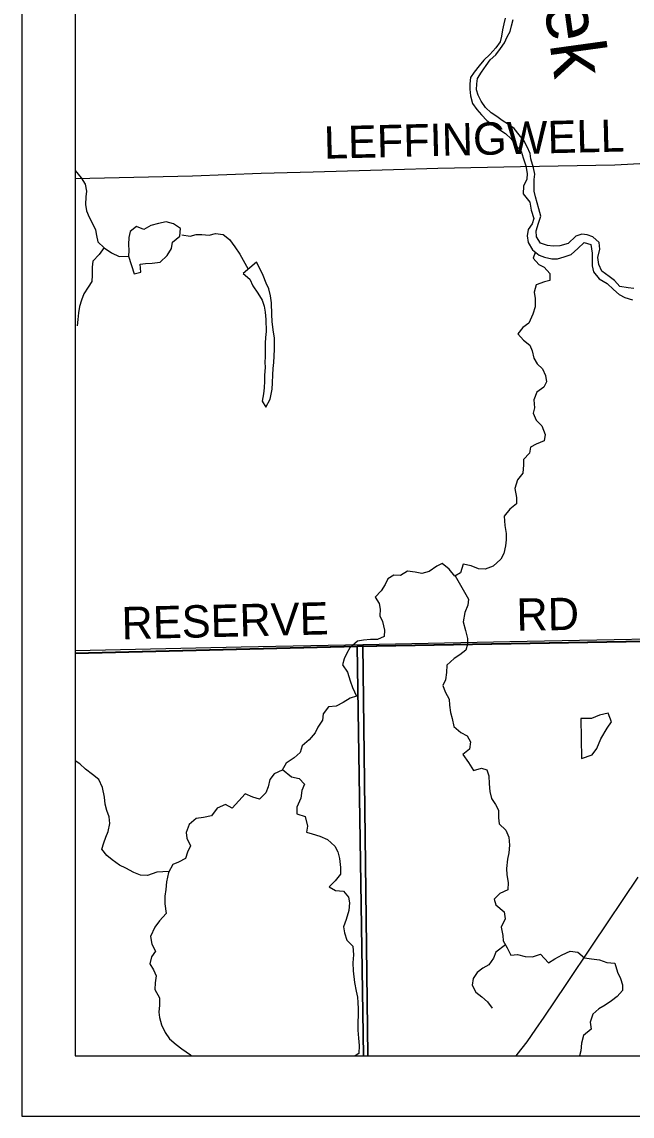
# Model space of a CAD drawing. Extents: x 0 to 34, y 0 to 22.
# Drawn here: x 2.63 to 3.7, y 9.902 to 11.824 of the extents above; entities that cross this region are included whole.
import ezdxf

# ---------------------------------------------------------------- set-up
doc = ezdxf.new("R2010")
doc.units = 0
for name, color, linetype in [('GM_X_Corporation', 7, 'Continuous'), ('GM_X_County_Road', 7, 'Continuous'), ('GM_X_County_Road_Text', 7, 'Continuous'), ('GM_X_Minor_Lake', 7, 'Continuous'), ('GM_X_Minor_River', 7, 'Continuous'), ('GM_X_Minor_River_Text', 7, 'Continuous'), ('GM_X_Rail_Line', 7, 'Continuous'), ('GM_X_Township_Road', 7, 'Continuous'), ('SH_Data', 7, 'Continuous')]:
    doc.layers.add(name, color=color, linetype=linetype)

msp = doc.modelspace()

# ---------------------------------------------------------------- linework, layer by layer
at = {"layer": 'GM_X_Corporation'}
msp.add_lwpolyline([(6.7217, 15.9197), (5.5749, 15.8972), (5.1967, 15.8898), (4.4889, 15.8766), (2.7231, 15.8419), (2.7231, 10.7149), (3.2181, 10.7269), (4.6326, 10.7519), (5.2789, 10.7635), (5.571, 10.7686), (6.8097, 10.7901)], dxfattribs=at)
for points in [[(3.2288, 10.0075), (9.4322, 10.0075), (9.4266, 10.7304), (9.4256, 10.8527), (9.3392, 10.8506), (8.3328, 10.8251), (7.8767, 10.8135), (6.8339, 10.7907), (6.8097, 10.7901), (5.571, 10.7686), (5.2789, 10.7635), (4.6326, 10.7519), (3.2181, 10.7269)], [(3.2368, 10.0075), (4.267, 10.0075), (4.2548, 10.7474), (3.913, 10.7427), (3.486, 10.7347), (3.228, 10.7293)], [(2.7231, 10.7186), (2.7231, 10.0075), (3.2368, 10.0075), (3.228, 10.7293), (3.0146, 10.725)], [(2.7231, 10.7149), (2.7231, 10.0075), (3.2288, 10.0075), (3.2181, 10.7269)]]:
    msp.add_lwpolyline(points, close=True, dxfattribs=at)
at = {"layer": 'GM_X_County_Road'}
msp.add_line((2.7231, 10.7143), (3.2183, 10.7263), dxfattribs=at)
for points in [[(4.6159, 11.5926), (4.1469, 11.5863), (3.7686, 11.5769), (3.6702, 11.5721), (3.5046, 11.5687), (3.3595, 11.566), (3.2817, 11.5638), (3.1404, 11.5595), (3.0493, 11.5571), (2.9289, 11.5524), (2.7231, 11.5477)], [(3.2183, 10.7263), (4.6328, 10.7513), (5.2791, 10.763), (5.5712, 10.7681), (6.8099, 10.7896)]]:
    msp.add_lwpolyline(points, dxfattribs=at)
at = {"layer": 'GM_X_Minor_Lake'}
for points in [[(2.8266, 11.3808), (2.8386, 11.3841), (2.8369, 11.3977), (2.8467, 11.3994), (2.8584, 11.3997), (2.872, 11.4014), (2.8843, 11.4131), (2.8921, 11.4257), (2.8941, 11.4368), (2.9068, 11.4473), (2.9077, 11.4606), (2.8958, 11.4687), (2.8829, 11.4723), (2.8696, 11.4694), (2.8557, 11.4657), (2.8437, 11.459), (2.8307, 11.4641), (2.8195, 11.4555), (2.8171, 11.4448), (2.8169, 11.4327), (2.8171, 11.4217), (2.8169, 11.4122)], [(2.8169, 11.4122), (2.8266, 11.3808)], [(3.0179, 11.3814), (3.0298, 11.3717), (3.035, 11.3597), (3.0436, 11.3469), (3.051, 11.3345), (3.0546, 11.3243), (3.0567, 11.3134), (3.0577, 11.3009), (3.0581, 11.2796), (3.0571, 11.2693), (3.0565, 11.259), (3.0563, 11.2495), (3.0562, 11.2355), (3.056, 11.226), (3.0562, 11.2165), (3.0553, 11.2028), (3.0551, 11.1925), (3.0546, 11.1808), (3.0533, 11.1705), (3.0512, 11.1575), (3.0579, 11.147), (3.0652, 11.1608), (3.069, 11.1784), (3.0696, 11.1894), (3.0701, 11.2035), (3.0706, 11.2149), (3.0716, 11.2255), (3.0725, 11.2366), (3.0726, 11.2487), (3.0729, 11.2582), (3.0727, 11.2681), (3.0705, 11.2825), (3.0687, 11.2973), (3.0681, 11.3098), (3.0677, 11.3299), (3.066, 11.3424), (3.0627, 11.3545), (3.0584, 11.3647), (3.0532, 11.3783), (3.0481, 11.388), (3.041, 11.4012)], [(3.041, 11.4012), (3.0179, 11.3814)], [(3.6115, 10.5296), (3.6303, 10.5364), (3.6384, 10.5472), (3.6453, 10.5644), (3.6563, 10.5832), (3.6641, 10.594), (3.6585, 10.6091), (3.643, 10.6058), (3.6291, 10.5998), (3.6102, 10.6002)], [(3.6102, 10.6002), (3.6115, 10.5296)]]:
    msp.add_lwpolyline(points, dxfattribs=at)
at = {"layer": 'GM_X_Minor_River'}
msp.add_line((2.7231, 11.5631), (2.7232, 11.5623), dxfattribs=at)
for points in [[(3.4777, 11.8299), (3.4751, 11.82), (3.4729, 11.8093), (3.4711, 11.7983), (3.4686, 11.7884), (3.4614, 11.7777), (3.4509, 11.7662), (3.4403, 11.7562), (3.432, 11.7466), (3.4234, 11.7352), (3.417, 11.7256), (3.4156, 11.7146), (3.4157, 11.7051), (3.4165, 11.6937), (3.4201, 11.6804), (3.4278, 11.6698), (3.4358, 11.66), (3.4454, 11.6502), (3.4562, 11.6419), (3.4665, 11.6348), (3.478, 11.6273), (3.4883, 11.6179), (3.4956, 11.6077), (3.5056, 11.5963), (3.5092, 11.5846), (3.5138, 11.5708)], [(3.5275, 11.5673), (3.5225, 11.5828), (3.5213, 11.5923), (3.5162, 11.604), (3.51, 11.6154), (3.502, 11.6252), (3.4931, 11.6361), (3.4835, 11.6433), (3.4724, 11.6504), (3.4629, 11.6576), (3.4529, 11.664), (3.4433, 11.673), (3.4353, 11.6843), (3.4302, 11.6946), (3.4275, 11.7044), (3.4278, 11.7147), (3.4292, 11.7242), (3.4363, 11.7349), (3.4442, 11.7471), (3.451, 11.7567), (3.4612, 11.7659), (3.4694, 11.7766), (3.4766, 11.7869), (3.481, 11.7972), (3.4863, 11.8068), (3.4889, 11.8163), (3.4914, 11.8277)], [(3.5138, 11.5708), (3.5163, 11.5575), (3.5157, 11.5473), (3.5095, 11.535), (3.5094, 11.5213), (3.5206, 11.5067), (3.5232, 11.4931), (3.5276, 11.4784), (3.5247, 11.4688), (3.5181, 11.4588), (3.516, 11.4478), (3.5178, 11.436), (3.5252, 11.4232), (3.5371, 11.4136), (3.5467, 11.4104), (3.5592, 11.4076), (3.5695, 11.4074), (3.5811, 11.4106), (3.5932, 11.415), (3.6051, 11.4255), (3.6163, 11.436), (3.6281, 11.4328), (3.6303, 11.4173), (3.6301, 11.4066), (3.6299, 11.3948), (3.6324, 11.3846), (3.6425, 11.3723), (3.6567, 11.3638), (3.6675, 11.3534), (3.6778, 11.3448), (3.6874, 11.3393), (3.7007, 11.3354)], [(2.7232, 11.5623), (2.7337, 11.5496), (2.7407, 11.5387), (2.7432, 11.5262), (2.7419, 11.516), (2.7413, 11.5027), (2.7431, 11.4917), (2.7478, 11.4808), (2.7529, 11.4706), (2.7585, 11.4585), (2.7605, 11.4483), (2.763, 11.437), (2.7742, 11.4269), (2.7869, 11.4181), (2.8002, 11.4115), (2.8169, 11.4122)], [(3.7034, 11.3552), (3.6935, 11.3562), (3.6787, 11.3585), (3.6694, 11.3694), (3.6598, 11.3764), (3.6472, 11.3857), (3.6416, 11.3973), (3.6399, 11.4098), (3.6434, 11.4243), (3.6424, 11.4361), (3.6313, 11.4461), (3.6213, 11.4494), (3.6118, 11.4507), (3.6013, 11.4471), (3.5879, 11.4343), (3.5736, 11.4299), (3.5618, 11.4296), (3.552, 11.431), (3.5398, 11.4349), (3.5328, 11.4458), (3.5322, 11.4564), (3.5361, 11.4698), (3.54, 11.4824), (3.5368, 11.4953), (3.5339, 11.5055), (3.5307, 11.516), (3.5286, 11.5259), (3.5284, 11.5373), (3.5286, 11.5468), (3.5296, 11.5563), (3.5275, 11.5673)], [(2.9102, 11.4492), (2.9246, 11.4469), (2.9356, 11.4501), (2.9454, 11.4503), (2.9583, 11.449), (2.9692, 11.4519), (2.9825, 11.4502), (2.9937, 11.4413), (3.0034, 11.4286), (3.0123, 11.4155), (3.0268, 11.389)], [(2.7737, 11.4274), (2.7653, 11.415), (2.7542, 11.4034), (2.7529, 11.3927), (2.7531, 11.3787), (2.7526, 11.3673), (2.7459, 11.3576), (2.7382, 11.3461), (2.7342, 11.335), (2.731, 11.3236), (2.729, 11.3125), (2.728, 11.3007), (2.7267, 11.2897)], [(3.5306, 11.4189), (3.5302, 11.4184), (3.5266, 11.4085), (3.5367, 11.3973), (3.5462, 11.3925), (3.5559, 11.3813), (3.5561, 11.3695), (3.5463, 11.3667), (3.532, 11.3615), (3.5285, 11.3489), (3.5302, 11.3375), (3.5301, 11.3231), (3.5262, 11.3104), (3.5193, 11.2944), (3.5084, 11.2866), (3.4999, 11.2758), (3.5096, 11.2642), (3.5207, 11.2556), (3.5251, 11.2459), (3.5276, 11.233), (3.5335, 11.2232), (3.5431, 11.2139), (3.5483, 11.2022), (3.55, 11.1912), (3.5456, 11.1817), (3.5329, 11.1731), (3.5278, 11.1597), (3.5292, 11.1457), (3.5267, 11.1361), (3.5319, 11.1237), (3.5419, 11.114), (3.5475, 11.0989), (3.5462, 11.0875), (3.5319, 11.0819), (3.5222, 11.0768), (3.5201, 11.0661), (3.5097, 11.0549), (3.5099, 11.0454), (3.5086, 11.0309), (3.4994, 11.0194), (3.4947, 11.0041), (3.4977, 10.9882), (3.4975, 10.9768), (3.4855, 10.9678), (3.4755, 10.9551), (3.477, 10.9388), (3.4791, 10.9252), (3.479, 10.9138), (3.478, 10.9035), (3.4752, 10.8898), (3.4701, 10.8798), (3.4567, 10.8674), (3.4424, 10.8622), (3.4306, 10.8627), (3.4177, 10.8682), (3.404, 10.8709), (3.3993, 10.856), (3.3892, 10.8498), (3.3795, 10.8625), (3.3672, 10.8725), (3.3574, 10.8678), (3.3443, 10.8584), (3.3315, 10.8544), (3.3194, 10.8572), (3.3061, 10.8588), (3.2937, 10.8514), (3.2823, 10.8515), (3.2715, 10.8456), (3.2671, 10.8353), (3.2601, 10.8245), (3.2493, 10.8133), (3.2563, 10.8021), (3.2584, 10.7922), (3.2579, 10.7801), (3.2622, 10.7703), (3.2656, 10.7551), (3.265, 10.7441), (3.2534, 10.7386), (3.2412, 10.7387), (3.2287, 10.7377), (3.2185, 10.736), (3.2051, 10.7244), (3.2, 10.7148), (3.1953, 10.7048), (3.192, 10.6941), (3.201, 10.6814), (3.2058, 10.6663), (3.2098, 10.6546), (3.2169, 10.6395), (3.2053, 10.6355), (3.1933, 10.628), (3.1809, 10.6217), (3.1676, 10.6203), (3.1584, 10.6084), (3.1571, 10.5973), (3.1486, 10.5846), (3.1442, 10.5747), (3.1339, 10.5623), (3.1216, 10.5519), (3.1176, 10.54), (3.1075, 10.5307)], [(3.3901, 10.8503), (3.4131, 10.8096), (3.4121, 10.7993), (3.4067, 10.7859), (3.4039, 10.7699), (3.408, 10.7548), (3.4113, 10.7408), (3.4115, 10.7305), (3.4083, 10.7202), (3.3978, 10.7117), (3.3881, 10.7054), (3.3751, 10.6934), (3.3745, 10.6808), (3.3729, 10.6679), (3.3681, 10.6579), (3.3721, 10.647), (3.3792, 10.6342), (3.3801, 10.6232), (3.3815, 10.6103), (3.3847, 10.6001), (3.3877, 10.5857), (3.4, 10.5753), (3.4107, 10.5698), (3.4169, 10.5593), (3.4149, 10.5464), (3.4033, 10.537), (3.4131, 10.5228), (3.422, 10.5089), (3.436, 10.5126), (3.4455, 10.5101), (3.4487, 10.4992), (3.4494, 10.4851), (3.4504, 10.4718), (3.4533, 10.4594), (3.4607, 10.4492), (3.4658, 10.4391), (3.4656, 10.4254), (3.467, 10.4148), (3.4785, 10.404), (3.4841, 10.3916), (3.4851, 10.3775), (3.4842, 10.3638), (3.4818, 10.3532), (3.4798, 10.3364), (3.4804, 10.3254), (3.4829, 10.3122), (3.4824, 10.2988), (3.4681, 10.2925), (3.4584, 10.2828), (3.4613, 10.2726), (3.4759, 10.2604), (3.4773, 10.2479), (3.4707, 10.2333), (3.4736, 10.2189), (3.4742, 10.2094), (3.4809, 10.197), (3.4872, 10.1846), (3.4989, 10.1856), (3.5126, 10.182), (3.5255, 10.1815), (3.5394, 10.186), (3.5533, 10.171), (3.5649, 10.1781), (3.5773, 10.1848), (3.5916, 10.1915), (3.6049, 10.1895), (3.6165, 10.1795), (3.629, 10.1778), (3.643, 10.1762), (3.656, 10.1715), (3.6697, 10.1702), (3.6745, 10.1547), (3.6796, 10.1434), (3.6836, 10.1321), (3.6834, 10.1222), (3.6742, 10.1118), (3.6641, 10.104), (3.6532, 10.0966), (3.6416, 10.0899), (3.6315, 10.0806), (3.6265, 10.0668), (3.6282, 10.0543), (3.6152, 10.0434), (3.6113, 10.0297), (3.6104, 10.0164), (3.608, 10.0075)], [(2.8875, 10.331), (2.8661, 10.3301), (2.8503, 10.3245), (2.8378, 10.325), (2.826, 10.3294), (2.8118, 10.3371), (2.8011, 10.3422), (2.7881, 10.3518), (2.7784, 10.3596), (2.7699, 10.3705), (2.7735, 10.3816), (2.7771, 10.3915), (2.7811, 10.4015), (2.7838, 10.4156), (2.7829, 10.4273), (2.7785, 10.4383), (2.776, 10.4496), (2.7743, 10.4617), (2.7713, 10.4788), (2.7646, 10.4931), (2.7538, 10.5016), (2.7415, 10.5113), (2.7311, 10.5202), (2.7231, 10.5255)], [(3.1075, 10.5307), (3.0933, 10.5213), (3.086, 10.509), (3.0724, 10.5031), (3.0647, 10.493), (3.0619, 10.4797), (3.0579, 10.4694), (3.0468, 10.4581), (3.0346, 10.4621), (3.0212, 10.4675), (3.0104, 10.4552), (2.9985, 10.4428), (2.9871, 10.4487), (2.972, 10.4423), (2.9621, 10.4288), (2.9481, 10.4259), (2.9356, 10.4245), (2.9229, 10.4136), (2.9179, 10.3995), (2.9188, 10.39), (2.9255, 10.3765), (2.9204, 10.365), (2.9168, 10.3539), (2.9044, 10.3476), (2.8947, 10.3436), (2.8866, 10.3294), (2.8835, 10.3134), (2.8822, 10.2997), (2.8802, 10.2879), (2.8804, 10.2746), (2.883, 10.2575), (2.8711, 10.2444), (2.8626, 10.2336), (2.855, 10.2171), (2.8579, 10.2039), (2.8642, 10.1911), (2.8568, 10.1814), (2.854, 10.1689), (2.8606, 10.1583), (2.865, 10.1482), (2.8633, 10.136), (2.8628, 10.1238), (2.871, 10.1092), (2.8712, 10.0963), (2.8699, 10.0845), (2.8712, 10.0746), (2.8745, 10.0621), (2.8808, 10.0486), (2.8886, 10.0373), (2.9005, 10.0277), (2.9101, 10.0199), (2.9255, 10.0092), (2.9274, 10.0075)], [(3.0867, 10.5102), (3.1029, 10.4976), (3.1162, 10.4948), (3.1254, 10.4847), (3.1207, 10.4736), (3.1191, 10.4603), (3.1122, 10.4442), (3.112, 10.4328), (3.1265, 10.4277), (3.131, 10.4111), (3.1289, 10.4004), (3.1392, 10.3972), (3.1521, 10.3933), (3.1659, 10.3875), (3.1786, 10.3759), (3.1841, 10.3658), (3.1866, 10.3544), (3.1888, 10.3381), (3.1886, 10.3267), (3.1794, 10.3148), (3.169, 10.3043), (3.1801, 10.2981), (3.1941, 10.2968), (3.2026, 10.286), (3.2047, 10.2761), (3.2034, 10.2628), (3.1988, 10.2472), (3.1941, 10.2342), (3.1955, 10.2235), (3.1995, 10.2107), (3.2103, 10.2003), (3.2117, 10.1847), (3.2101, 10.171), (3.2107, 10.1566), (3.2134, 10.1361), (3.2163, 10.121), (3.2184, 10.1108), (3.2189, 10.1013), (3.2199, 10.0903), (3.2197, 10.08), (3.2188, 10.0652), (3.2191, 10.0527), (3.2205, 10.0386), (3.2215, 10.0254), (3.2206, 10.0117), (3.2142, 10.0075)], [(3.4781, 10.2023), (3.4613, 10.1894), (3.4573, 10.1791), (3.4488, 10.1675), (3.4383, 10.1617), (3.4286, 10.1539), (3.4212, 10.1435), (3.4199, 10.1317), (3.4258, 10.1196), (3.4366, 10.1111), (3.4466, 10.1026), (3.4548, 10.0913)]]:
    msp.add_lwpolyline(points, dxfattribs=at)
at = {"layer": 'GM_X_Rail_Line'}
msp.add_lwpolyline([(3.4969, 10.0075), (3.4986, 10.0097), (3.5159, 10.0319), (3.5315, 10.0541), (3.546, 10.0753), (3.5845, 10.1326), (3.6308, 10.2018), (3.7111, 10.3214)], dxfattribs=at)
at = {"layer": 'GM_X_Township_Road'}
msp.add_line((3.229, 10.0075), (3.2183, 10.7263), dxfattribs=at)
at = {"layer": 'SH_Data'}
for p, q in [((2.6297, 16.9017), (2.6297, 9.9017)), ((2.6297, 9.9017), (9.6297, 9.9017))]:
    msp.add_line(p, q, dxfattribs=at)

# ---------------------------------------------------------------- texts
at = {"layer": 'GM_X_County_Road_Text'}
for s, height, rotation, p in [('LEFFINGWELL', 0.056818, 1.397, (3.1601, 11.5831)), ('RESERVE', 0.05682, 1.3932, (2.8052, 10.739)), ('RD', 0.05682, 0.9872, (3.4978, 10.7539))]:
    msp.add_text(s, height=height, rotation=rotation, dxfattribs=at).set_placement(p)
at = {"layer": 'GM_X_Minor_River_Text'}
msp.add_text('Creek', height=0.09474, rotation=277.8683, dxfattribs=at).set_placement((3.5179, 12.0569))

doc.saveas('drawing.dxf')
